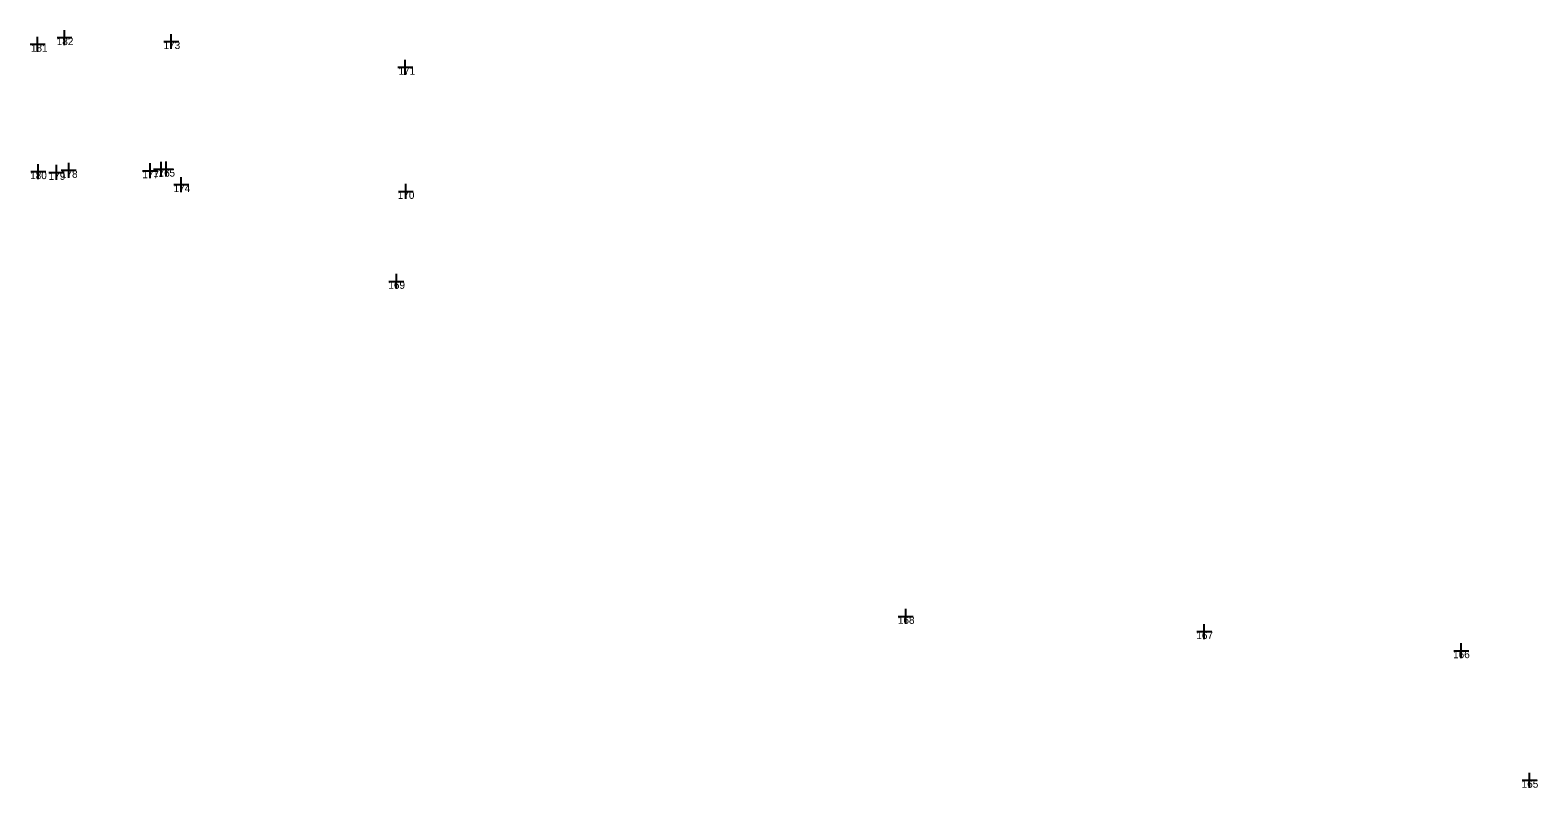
# Model space of a CAD drawing. Extents: x -706655 to -706193, y -1036183 to -1034979.
# Drawn here: x -706405.4 to -706304.4, y -1035940.9 to -1035890.2 of the extents above; entities that cross this region are included whole.
import ezdxf

# ---------------------------------------------------------------- set-up
doc = ezdxf.new("R2010")
doc.units = 0
doc.layers.add('čísla bodu', color=7, linetype='Continuous')

msp = doc.modelspace()

# ---------------------------------------------------------------- linework, layer by layer
at = {"layer": 'čísla bodu'}
for p, q in [((-706403.07, -1035891.24), (-706403.07, -1035890.24)), ((-706405.37, -1035891.18), (-706404.37, -1035891.18)), ((-706404.87, -1035891.68), (-706404.87, -1035890.68)), ((-706404.87, -1035891.18), (-706404.87, -1035891.18)), ((-706403.57, -1035890.74), (-706402.57, -1035890.74)), ((-706403.07, -1035890.74), (-706403.07, -1035890.74)), ((-706396.42, -1035891), (-706395.42, -1035891)), ((-706395.92, -1035891.5), (-706395.92, -1035890.5)), ((-706395.92, -1035891), (-706395.92, -1035891)), ((-706380.26, -1035893.22), (-706380.26, -1035892.22)), ((-706380.76, -1035892.72), (-706379.76, -1035892.72)), ((-706380.26, -1035892.72), (-706380.26, -1035892.72)), ((-706404.83, -1035900.21), (-706404.83, -1035899.21)), ((-706403.61, -1035900.26), (-706403.61, -1035899.26)), ((-706402.79, -1035900.12), (-706402.79, -1035899.12)), ((-706397.34, -1035900.15), (-706397.34, -1035899.15)), ((-706396.61, -1035900.05), (-706396.61, -1035899.05)), ((-706396.27, -1035900.04), (-706396.27, -1035899.04)), ((-706405.33, -1035899.71), (-706404.33, -1035899.71)), ((-706404.83, -1035899.71), (-706404.83, -1035899.71)), ((-706404.11, -1035899.76), (-706403.11, -1035899.76)), ((-706403.61, -1035899.76), (-706403.61, -1035899.76)), ((-706403.29, -1035899.62), (-706402.29, -1035899.62)), ((-706402.79, -1035899.62), (-706402.79, -1035899.62)), ((-706397.84, -1035899.65), (-706396.84, -1035899.65)), ((-706397.34, -1035899.65), (-706397.34, -1035899.65)), ((-706397.11, -1035899.55), (-706396.11, -1035899.55)), ((-706396.77, -1035899.54), (-706395.77, -1035899.54)), ((-706396.61, -1035899.55), (-706396.61, -1035899.55)), ((-706396.27, -1035899.54), (-706396.27, -1035899.54)), ((-706395.25, -1035901.08), (-706395.25, -1035900.08)), ((-706395.75, -1035900.58), (-706394.75, -1035900.58)), ((-706395.25, -1035900.58), (-706395.25, -1035900.58)), ((-706380.72, -1035901.03), (-706379.72, -1035901.03)), ((-706380.22, -1035901.53), (-706380.22, -1035900.53)), ((-706380.22, -1035901.03), (-706380.22, -1035901.03)), ((-706381.35, -1035907.05), (-706380.35, -1035907.05)), ((-706380.85, -1035907.55), (-706380.85, -1035906.55)), ((-706380.85, -1035907.05), (-706380.85, -1035907.05)), ((-706347.25, -1035929.47), (-706346.25, -1035929.47)), ((-706346.75, -1035929.97), (-706346.75, -1035928.97)), ((-706346.75, -1035929.47), (-706346.75, -1035929.47)), ((-706327.27, -1035930.49), (-706326.27, -1035930.49)), ((-706326.77, -1035930.99), (-706326.77, -1035929.99)), ((-706326.77, -1035930.49), (-706326.77, -1035930.49)), ((-706309.56, -1035932.27), (-706309.56, -1035931.27)), ((-706310.06, -1035931.77), (-706309.06, -1035931.77)), ((-706309.56, -1035931.77), (-706309.56, -1035931.77)), ((-706305.49, -1035940.44), (-706304.49, -1035940.44)), ((-706304.99, -1035940.94), (-706304.99, -1035939.94)), ((-706304.99, -1035940.44), (-706304.99, -1035940.44))]:
    msp.add_line(p, q, dxfattribs=at)

# ---------------------------------------------------------------- texts
for s, p in [('181', (-706405.32, -1035891.68)), ('182', (-706403.59, -1035891.24)), ('173', (-706396.44, -1035891.5)), ('171', (-706380.71, -1035893.22)), ('180', (-706405.37, -1035900.21)), ('179', (-706404.13, -1035900.26)), ('178', (-706403.31, -1035900.12)), ('177', (-706397.86, -1035900.15)), ('176', (-706397.14, -1035900.05)), ('175', (-706396.79, -1035900.04)), ('174', (-706395.77, -1035901.08)), ('170', (-706380.76, -1035901.53)), ('169', (-706381.39, -1035907.55)), ('168', (-706347.28, -1035929.97)), ('167', (-706327.3, -1035930.99)), ('166', (-706310.11, -1035932.27)), ('165', (-706305.52, -1035940.94))]:
    msp.add_text(s, height=0.5, dxfattribs=at).set_placement(p)

doc.saveas('drawing.dxf')
